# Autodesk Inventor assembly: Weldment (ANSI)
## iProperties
Length Units: 11272
Angle Units: 11286
Time Units: 11279
Mass Units: 11290
Length Display Precision: 3
Angle Display Precision: 2
Part Number: Weldment (ANSI)
Document SubType Name: Weldment
Created: 2002-06
Designer: smithga
Part Number: Gondola_Bottom_alternate_support
Created: 2005-05
Designer: John Blackburn
Manufacturer: Standard
Standards Organization: Custom
Control State: 0
Master: False
Shininess: 64.0
Angle Units: 11279
Time Units: 11290
Mass Units: 11286
Compacted: True
Density: 0.0
Volumn: 0.0
Area: 0.0
PropertySet Name: Model Information
Author: John Blackburn
